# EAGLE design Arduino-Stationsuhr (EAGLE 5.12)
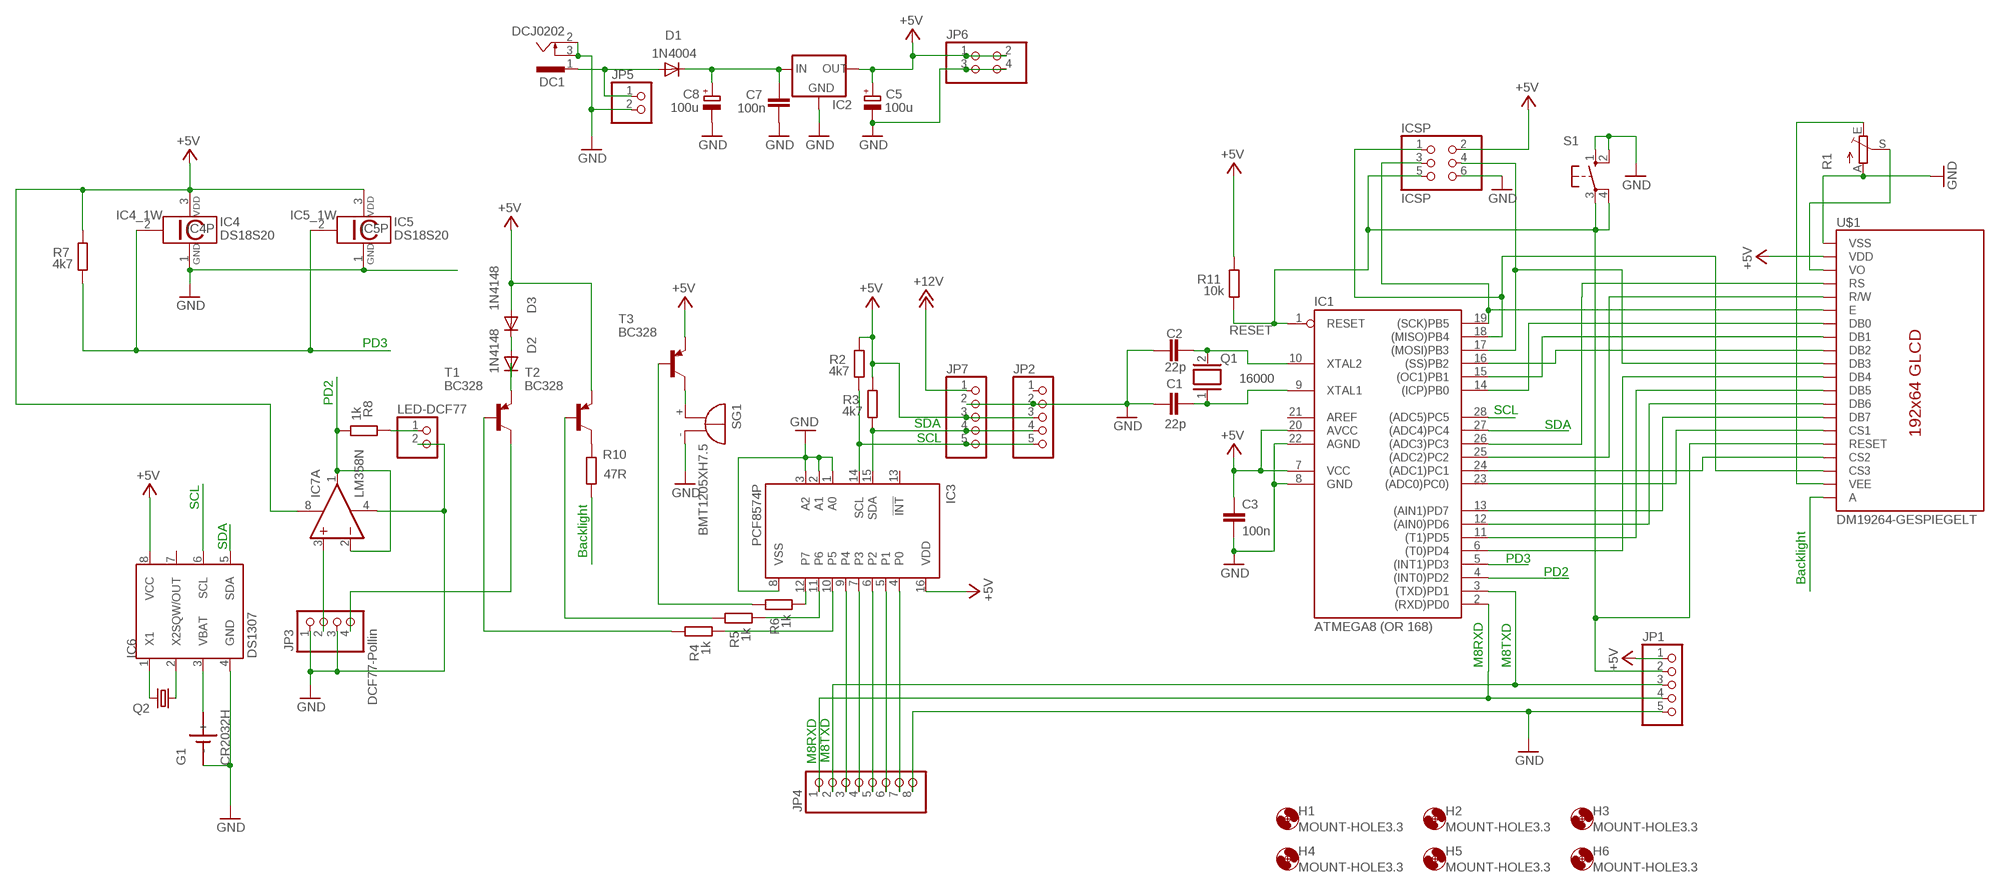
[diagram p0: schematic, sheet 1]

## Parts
C1  22p  C-EU025-024X044  [C025-024X044]
C2  22p  C-EU025-024X044  [C025-024X044]
C3  100n  C-5-1  [C-5-1]
C5  100u  CPOL-EUE3.5-8  [E3,5-8]
C7  100n  C-5-1  [C-5-1]
C8  100u  CPOL-EUE3.5-8  [E3,5-8]
D1  1N4004  1N4148  [DO35-10]
D2  1N4148  1N4148DO35-10  [DO35-10]
D3  1N4148  1N4148DO35-10  [DO35-10]
DC1  DCJ0202  733980-62  [733980-62]
G1  CR2032H  SN2032  [SN2032]
H1  MOUNT-HOLE3.3  [3,3]
H2  MOUNT-HOLE3.3  [3,3]
H3  MOUNT-HOLE3.3  [3,3]
H4  MOUNT-HOLE3.3  [3,3]
H5  MOUNT-HOLE3.3  [3,3]
H6  MOUNT-HOLE3.3  [3,3]
IC1  ATMEGA8 (OR 168)  AT90S4433P  [DIL28-3]
IC2  78XXL  [78XXL]
IC3  PCF8574P  [DIL16]
IC4  DS18S20  [TO92-]
IC5  DS18S20  [TO92-]
IC6  DS1307  DS1307DIL-8  [DIL08]
IC7  LM358N  [DIL08]
ICSP  ICSP  PINHD-2X3  [2X03]
JP1  PINHD-1X5/90  [1X05/90]
JP2  PINHD-1X5  [1X05]
JP3  DCF77-Pollin  PINHD-1X4  [1X04]
JP4  PINHD-1X8  [1X08]
JP5  PINHD-1X2  [1X02]
JP6  PINHD-2X2  [2X02]
JP7  PINHD-1X5  [1X05]
LED-DCF77  PINHD-1X2  [1X02]
Q1  16000  XTAL/S  [QS]
Q2  CRYSTALTC26H  [TC26H]
R1  TRIM_EU-LI10  [LI10]
R2  4k7  R-EU_0207/10  [0207/10]
R3  4k7  R-EU_0207/10  [0207/10]
R4  1k  R-EU_0207/10  [0207/10]
R5  1k  R-EU_0207/10  [0207/10]
R6  1k  R-EU_0207/10  [0207/10]
R7  4k7  R-EU_0207/10  [0207/10]
R8  1k  R-EU_0207/10  [0207/10]
R10  47R  R-EU_0207/10  [0207/10]
R11  10k  R-EU_0207/10  [0207/10]
S1  10-XX  [B3F-10XX]
SG1  BMT1205XH7.5  [BMT1205XH7.5]
T1  BC328  -PNP-TO92-CBE  [TO92-CBE]
T2  BC328  BC328-25  [TO92-EBC]
T3  BC328  BC328-25  [TO92-EBC]
U$1  DM19264-GESPIEGELT  [DM19265-GESPIEGELT]

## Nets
+5V [power]: C3.P$1 C5.+ D3.A IC1.7(VCC) IC1.20(AVCC) IC2.OUT IC3.16(VDD) IC4.3 IC5.3 IC6.8(VCC) IC7.8(P:V+) ICSP.2 JP1.1 JP2.3 JP6.1 JP6.2 JP7.3 R2.2 R3.2 R7.2 R11.2 T2.E T3.E U$1.2(VDD)
+12V: D1.A DC1.1 JP5.1
BACKLIGHT: R10.1 U$1.20(A)
GND: C1.1 C2.1 C3.P$2 C5.- C7.P$1 C8.- DC1.2 DC1.3 G1.- IC1.8(GND) IC1.22(AGND) IC2.GND IC3.1(A0) IC3.2(A1) IC3.3(A2) IC3.8(VSS) IC4.1 IC5.1 IC6.4(GND) IC7.4(P:V-) ICSP.6 JP1.5 JP2.2 JP3.1 JP3.3 JP4.8 JP5.2 JP6.3 JP6.4 JP7.2 LED-DCF77.2 R1.A S1.1(S) S1.2(S1) SG1.- U$1.1(VSS)
M8RXD: IC1.2((RXD)PD0) JP1.4 JP4.1
M8TXD: IC1.3((TXD)PD1) JP1.3 JP4.2
N$1: IC1.18((MISO)PB4) ICSP.1 U$1.18(CS3)
N$2: R1.S U$1.3(VO)
N$3: IC3.9(P4) JP4.3
N$4: IC1.17((MOSI)PB3) ICSP.4 U$1.10(DB3)
N$5: IC1.26((ADC3)PC3) U$1.4(RS)
N$6: C1.2 IC1.9(XTAL1) Q1.1
N$7: C2.2 IC1.10(XTAL2) Q1.2
N$8: IC7.3(A:+IN) JP3.2
N$9: IC1.25((ADC2)PC2) U$1.5(R/W)
N$10: IC1.14((ICP)PB0) U$1.7(DB0)
N$11: IC1.15((OC1)PB1) U$1.8(DB1)
N$12: IC1.16((SS)PB2) U$1.9(DB2)
N$13: IC6.1(X1) Q2.2
N$14: IC1.6((T0)PD4) U$1.11(DB4)
N$15: IC1.11((T1)PD5) U$1.12(DB5)
N$16: IC1.12((AIN0)PD6) U$1.13(DB6)
N$17: IC1.13((AIN1)PD7) U$1.14(DB7)
N$18: IC1.23((ADC0)PC0)) U$1.15(CS1)
N$19: R4.2 T1.B
N$20: IC1.24((ADC1)PC1) U$1.17(CS2)
N$21: IC6.2(X2) Q2.1
N$22: G1.+ IC6.3(VBAT)
N$23: IC3.4(P0) JP4.7
N$24: IC3.5(P1) JP4.6
N$25: IC3.6(P2) JP4.5
N$26: IC3.7(P3) JP4.4
N$28: IC3.10(P5) R4.1
N$29: IC3.11(P6) R5.1
N$30: IC3.12(P7) R6.1
N$31: D2.C T1.E
N$32: R5.2 T2.B
N$33: R6.2 T3.B
N$34: JP3.4 T1.C
N$36: SG1.+ T3.C
N$41: LED-DCF77.1 R8.2
N$42: R1.E U$1.19(VEE)
N$53: R10.2 T2.C
N$54 [power]: D2.A D3.C
PD2: IC1.4((INT0)PD2) IC7.1(A:OUT) IC7.2(A:-IN) R8.1
PD3: IC1.5((INT1)PD3) IC4.2 IC5.2 R7.1
RESET: IC1.1(RESET) ICSP.5 JP1.2 R11.1 S1.3(P) S1.4(P1) U$1.16(RESET)
SCK: IC1.19((SCK)PB5) ICSP.3 U$1.6(E)
SCL: IC1.28((ADC5)PC5) IC3.14(SCL) IC6.6(SCL) JP2.5 JP7.5 R2.1
SDA: IC1.27((ADC4)PC4) IC3.15(SDA) IC6.5(SDA) JP2.4 JP7.4 R3.1
VIN [power]: C7.P$2 C8.+ D1.C IC2.IN JP7.1 ; supply symbol labelled +12V
Unconnected: IC3.13(!INT) IC6.7(SQW/OUT) IC7.5(B:+IN) IC7.6(B:-IN) IC7.7(B:OUT) JP2.1

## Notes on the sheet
- PD3
- PD2
- SCL
- SDA | SDA
- SCL
- SCL
- SDA
- Backlight
- PD3
- PD2
- Backlight
- M8RXD | M8TXD
- M8RXD | M8TXD

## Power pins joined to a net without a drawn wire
AREF: IC1.21(AREF)

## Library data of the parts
C1 C2 = rcl:C-EU: CAPACITOR, European symbol
C3 C7 = papa:C-5-1
C5 C8 = rcl:CPOL-EU: POLARIZED CAPACITOR, European symbol
D1 = papa:1N4148: DIODE
D2 D3 = diode:1N4148: DIODE
DC1 = con-conrad:73398?: FEMALE PRINT CONNECTOR Niedervolt-Steckverbinder Distributor Conrad
G1 = sn2032:SN2032: LI BATTERY
H1-H6 = holes:MOUNT-HOLE: MOUNTING HOLE with drill center marker
IC1 = atmel:AT90S4433: MICROCONTROLLER 4 Kbytes FLASH 128 bytes SRAM 256 bytes EEPROM UART 6-channel 10 bit ADC
IC2 = v-reg:78XXL: VOLTAGE REGULATOR
IC3 = micro-philips:PCF8574: I2C-Bus Remote 8-bit I/O expander http://www.semiconductors.philips.com/acrobat_download/datasheets/PCF8574_4.pdf; MPN: PCF8574PN; OC_FARNELL: 204020; OC_NEWARK: 11N8515
IC4 IC5 = 1wire:DS18S20: High Precision Digital Thermometer This chip provides a onewire thermosensor with approx. 0.5°C accuracy.A programmable over/undertemperure alarm is available. Notes: Vdd must be applied for accurate measurements at low temperatures, as the parasite power circuit otherwise heats the sensor. If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
IC6 = dallas-1:DS1307: I2C Serial RTC w/56 bytes battery backed RAM
IC7 = linear:LM358: OP AMP also LM158; LM258; LM2904 Source: http://cache.national.com/ds/LM/LM158.pdf
ICSP = pinhead:PINHD-2X3: PIN HEADER
JP1 JP2 JP7 = pinhead:PINHD-1X5: PIN HEADER
JP3 = pinhead:PINHD-1X4: PIN HEADER
JP4 = pinhead:PINHD-1X8: PIN HEADER
JP5 LED-DCF77 = pinhead:PINHD-1X2: PIN HEADER
JP6 = pinhead:PINHD-2X2: PIN HEADER
Q1 = special:XTAL/S: CRYSTAL
Q2 = crystal:CRYSTAL: CRYSTAL; OC_FARNELL: unknown; OC_NEWARK: unknown
R1 = pot:TRIM_EU-: POTENTIOMETER
R2-R8 R10 R11 = rcl:R-EU_: RESISTOR, European symbol
S1 = switch-omron:10-XX: OMRON SWITCH
SG1 = buzzer:BMT1205XH7.5: MAGNETIC TRANSDUCER; OC_FARNELL: unknown; OC_NEWARK: unknown
T1 = transistor-neu-to92:*-PNP-: PNP Transistror
T2 T3 = transistor-pnp:BC328*: PNP Transistror
U$1 = DM19264:DM19264-GESPIEGELT

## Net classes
1 power: width 0.61 mm

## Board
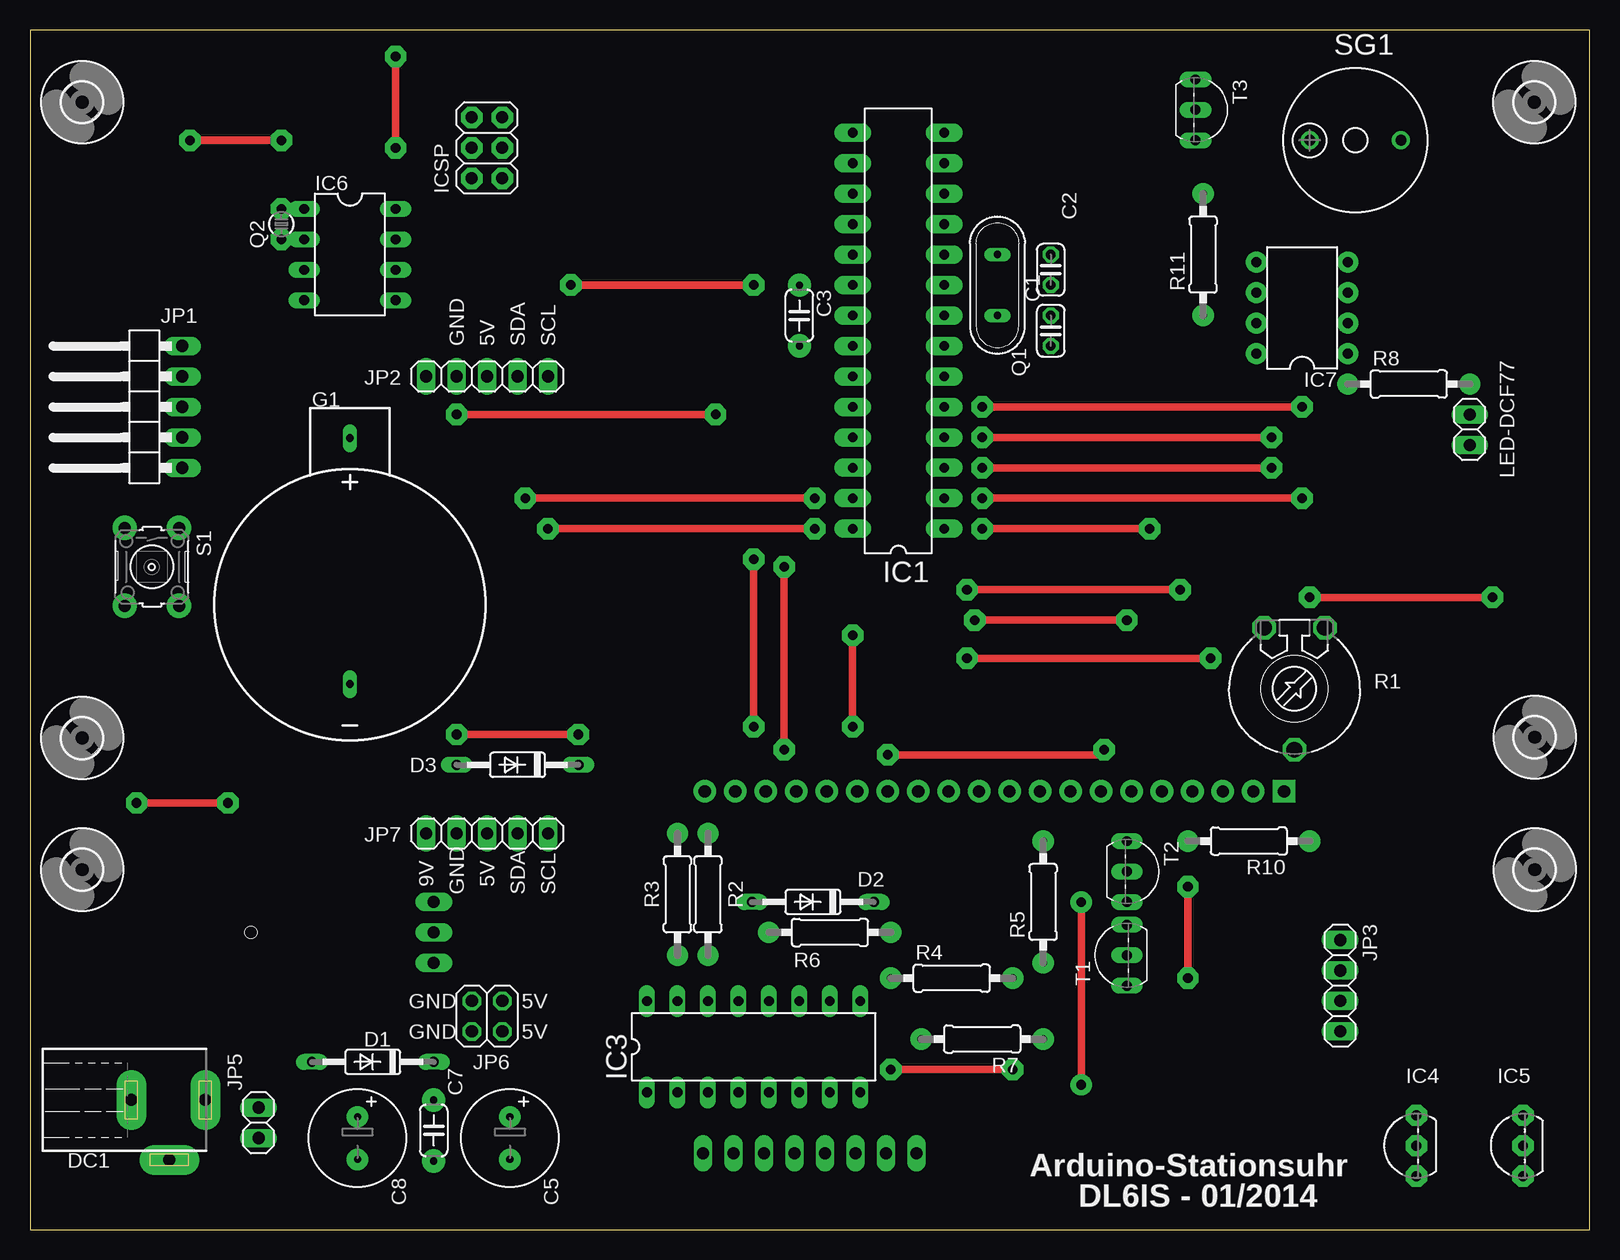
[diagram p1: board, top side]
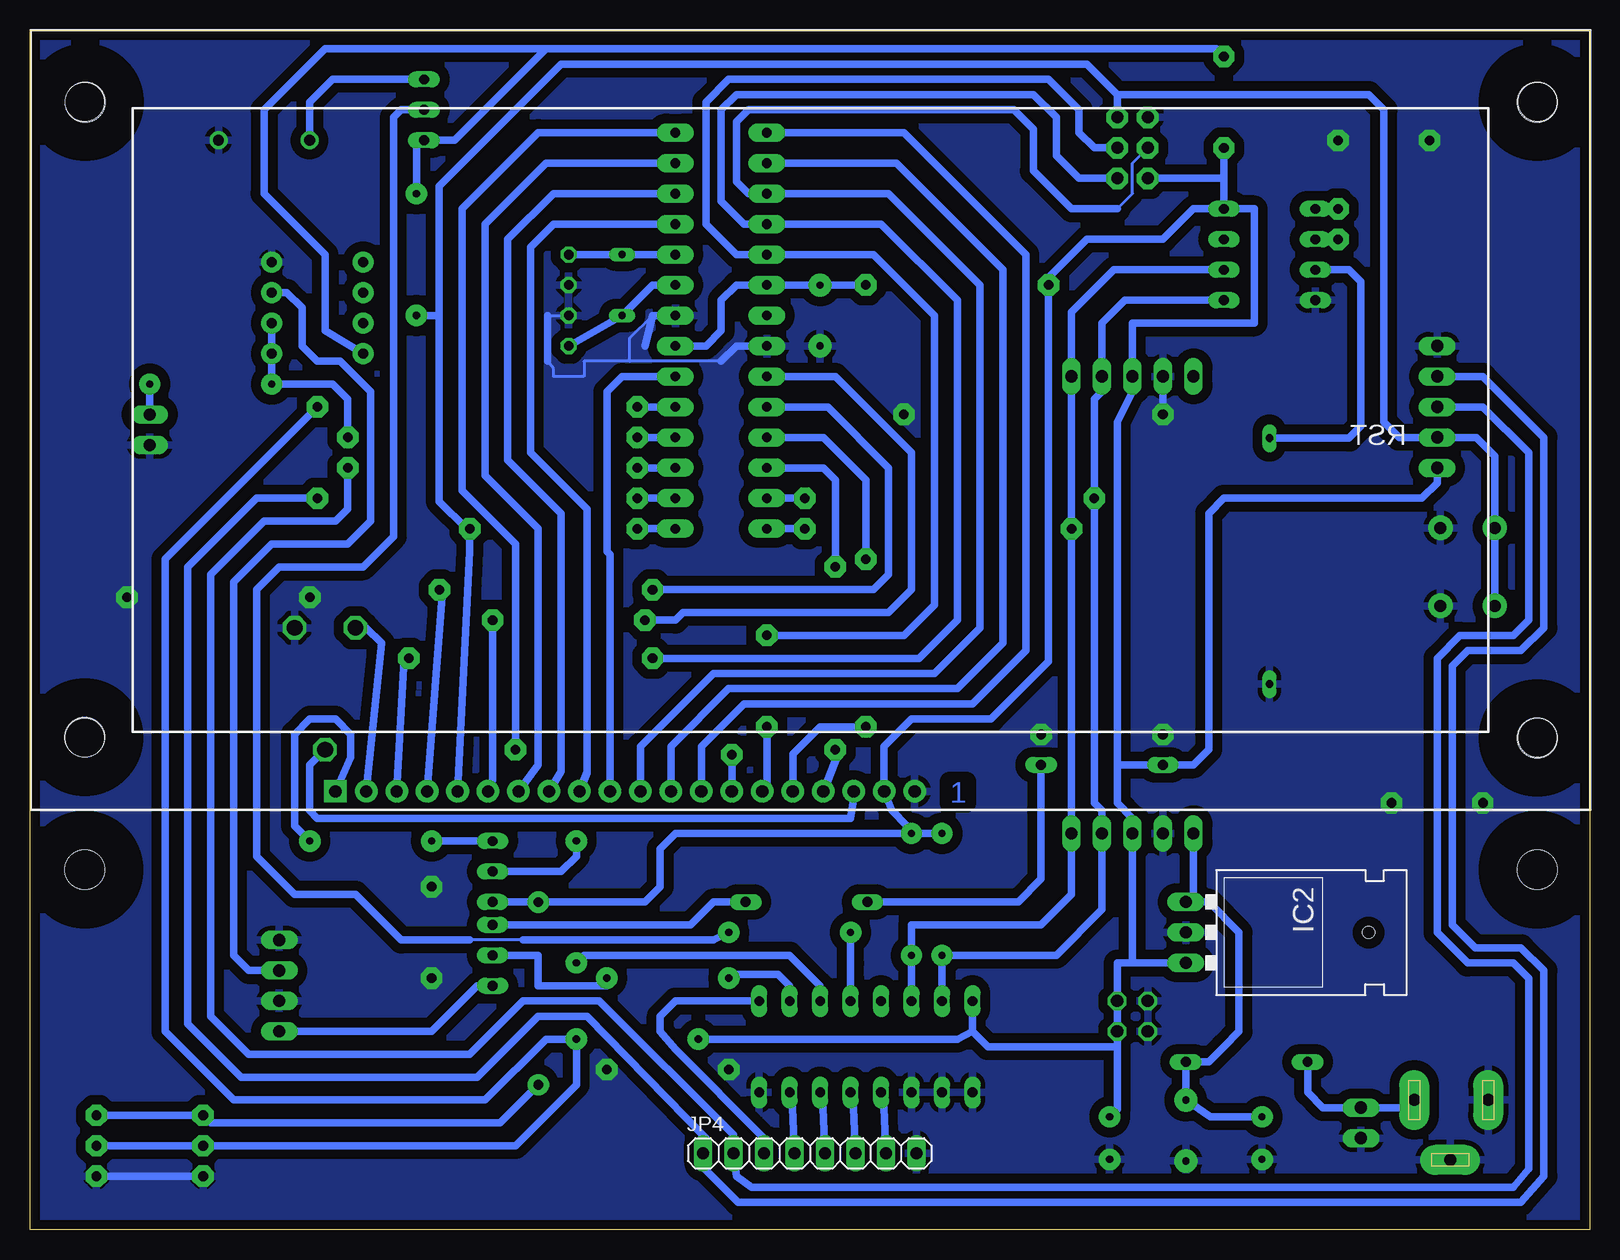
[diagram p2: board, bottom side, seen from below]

Size 130 x 100 mm. Coordinates in mm from the lower left corner, seen from the top.
Outline: 0,0 130,0 130,100 0,100 0,0
Copper layers (1*16): Top 0.035mm / dielectric 1.5mm / Bottom 0.035mm
Design rules "default *": minimum track width 10mil, minimum drill 24mil, track to track 8mil, track to pad 8mil, pad to pad 8mil, via to via 8mil, smd to smd 8mil, copper to edge 20mil, drill to drill 8mil, minimum pad ring 10mil, minimum via ring 10mil, stop-mask expansion 4mil, vias tented up to drill 0mil, thermal gap 16mil
Holes 1 mm at 18.41,24.77

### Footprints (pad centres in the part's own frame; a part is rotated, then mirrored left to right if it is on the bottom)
C025-024X044 = drill 0.813 octagon: 1 -1.27,0; 2 1.27,0
C-5-1 = drill 0.6 pad 1.93 round: P$1 -2.54,0; P$2 2.54,0
E3,5-8 = drill 0.6 pad 1.778 round: + -1.778,0; - 1.778,0
DO35-10 = drill 0.813 long: A 5.08,0; C -5.08,0
733980-62 = drill 1 pad 2.5 long: 1 0,8.57; 2 0,2.42; 3 5,5.57
SN2032 = drill 0.65 long: + 0,13.9; - 0,-6.6
3,3 = hole 3.3: 0,0
DIL28-3 = drill 0.813 pad 1.524 long: 1 -16.51,-3.81; 2 -13.97,-3.81; 3 -11.43,-3.81; 4 -8.89,-3.81; 5 -6.35,-3.81; 6 -3.81,-3.81; 7 -1.27,-3.81; 8 1.27,-3.81; 9 3.81,-3.81; 10 6.35,-3.81; 11 8.89,-3.81; 12 11.43,-3.81; 13 13.97,-3.81; 14 16.51,-3.81; 15 16.51,3.81; 16 13.97,3.81; 17 11.43,3.81; 18 8.89,3.81; 19 6.35,3.81; 20 3.81,3.81; 21 1.27,3.81; 22 -1.27,3.81; 23 -3.81,3.81; 24 -6.35,3.81; 25 -8.89,3.81; 26 -11.43,3.81; 27 -13.97,3.81; 28 -16.51,3.81
78XXL = drill 1.016 long: GND 0,-3.81; IN -2.54,-3.81; OUT 2.54,-3.81
DIL16 = drill 0.813 long: 1 -8.89,-3.81; 2 -6.35,-3.81; 3 -3.81,-3.81; 4 -1.27,-3.81; 5 1.27,-3.81; 6 3.81,-3.81; 7 6.35,-3.81; 8 8.89,-3.81; 9 8.89,3.81; 10 6.35,3.81; 11 3.81,3.81; 12 1.27,3.81; 13 -1.27,3.81; 14 -3.81,3.81; 15 -6.35,3.81; 16 -8.89,3.81
TO92- = drill 0.813 octagon: 1 -2.54,0; 2 0,0; 3 2.54,0
DIL08 = drill 0.813 long: 1 -3.81,-3.81; 2 -1.27,-3.81; 3 1.27,-3.81; 4 3.81,-3.81; 5 3.81,3.81; 6 1.27,3.81; 7 -1.27,3.81; 8 -3.81,3.81
DIL08' = drill 0.813 pad 1.27 round: 1 -3.81,-3.81; 2 -1.27,-3.81; 3 1.27,-3.81; 4 3.81,-3.81; 5 3.81,3.81; 6 1.27,3.81; 7 -1.27,3.81; 8 -3.81,3.81
2X03 = drill 1 pad 1.778 octagon: 1 -2.54,-1.27; 2 -2.54,1.27; 3 0,-1.27; 4 0,1.27; 5 2.54,-1.27; 6 2.54,1.27
1X05/90 = drill 1.016 long: 1 -5.08,-3.81; 2 -2.54,-3.81; 3 0,-3.81; 4 2.54,-3.81; 5 5.08,-3.81
1X05 = drill 1.016 long: 1 -5.08,0; 2 -2.54,0; 3 0,0; 4 2.54,0; 5 5.08,0
1X04 = drill 1.016 long: 1 -3.81,0; 2 -1.27,0; 3 1.27,0; 4 3.81,0
1X08 = drill 1.016 long: 1 -8.89,0; 2 -6.35,0; 3 -3.81,0; 4 -1.27,0; 5 1.27,0; 6 3.81,0; 7 6.35,0; 8 8.89,0
1X02 = drill 1.016 long: 1 -1.27,0; 2 1.27,0
2X02 = drill 1.016 octagon: 1 -1.27,-1.27; 2 -1.27,1.27; 3 1.27,-1.27; 4 1.27,1.27
QS = drill 0.61 long: 1 -2.54,0; 2 2.54,0
TC26V = drill 0.813 round: 1 -1.27,0; 2 1.27,0
LI10 = drill 1.321 octagon: A -2.54,-5.08; E 2.54,-5.08; S 0,5.08
0207/10 = drill 0.6 pad 1.778 round: 1 -5.08,0; 2 5.08,0
B3F-10XX = drill 1 pad 2.032 round: 1 -3.251,2.261; 2 3.251,2.261; 3 -3.251,-2.261; 4 3.251,-2.261
BMT1205XH7.5 = drill 0.9 pad 1.5 round: + 3.8,0; - -3.8,0
TO92-CBE = drill 0.813 long: B 0,0; C -2.54,0; E 2.54,0
TO92-EBC = drill 0.813 long: B 0,-1.27; C -2.54,-1.27; E 2.54,-1.27
DM19265-GESPIEGELT = drill 1.016 pad 1.88 round: 1 56.495,1.53; 2 59.035,1.53; 3 61.575,1.53; 4 64.115,1.53; 5 66.655,1.53; 6 69.195,1.53; 7 71.735,1.53; 8 74.275,1.53; 9 76.815,1.53; 10 79.355,1.53; 11 81.895,1.53; 12 84.435,1.53; 13 86.975,1.53; 14 89.515,1.53; 15 92.055,1.53; 16 94.595,1.53; 17 97.135,1.53; 18 99.675,1.53; 19 102.215,1.53 | drill 1.016 pad 1.88 square: 20 104.775,1.53 | hole 3.2: 125.675,59; 125.675,6; 4.575,59; 4.575,6

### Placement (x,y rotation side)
C1  85.09,74.93 270 top
C2  85.09,80.01 90 top
C3  64.14,76.2 270 top
C5  40.01,7.62 270 top
C7  33.66,8.26 90 top
C8  27.3,7.62 270 top
D1  28.57,13.97 180 top
D2  65.27,27.3 180 top
D3  40.64,38.73 180 top
DC1  6.04,10.79 270 top
G1  26.67,52.07 0 top
H1  4.34,30 0 top
H2  125.43,30 0 top
H3  4.34,93.98 0 top
H4  125.39,93.98 0 top
H5  4.34,40.98 0 top
H6  125.43,41.04 0 top
IC1  72.39,74.93 90 top
IC2  29.84,24.77 270 bottom
IC3  60.33,15.24 0 top
IC4  115.57,6.99 90 top
IC5  124.46,6.99 90 top
IC6  26.67,81.28 270 top
IC7  LM358N  [DIL08']  106.05,76.83 90 top
ICSP  38.1,90.17 90 top
JP1  8.89,68.58 90 top
JP2  38.1,71.12 0 top
JP3  109.22,20.32 270 top
JP4  65,6.35 0 bottom
JP5  19.05,8.89 270 top
JP6  38.1,17.78 180 top
JP7  38.1,33.02 0 top
LED-DCF77  120.02,66.67 270 top
Q1  80.64,78.74 90 top
Q2  [TC26V]  20.95,83.82 90 top
R1  105.41,45.09 180 top
R2  56.52,27.94 90 top
R3  53.98,27.94 90 top
R4  76.83,20.95 0 top
R5  84.45,27.3 90 top
R6  66.67,24.77 0 top
R7  79.38,15.88 180 top
R8  114.94,70.48 0 top
R10  101.6,32.38 180 top
R11  97.79,81.28 90 top
S1  10.16,55.24 270 top
SG1  110.49,90.81 180 top
T1  91.44,22.86 90 top
T2  92.71,29.84 270 top
T3  98.42,93.34 270 top
U$1  -0.24,35 0 top

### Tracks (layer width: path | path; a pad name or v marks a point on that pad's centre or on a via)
+5V  (via drill 0.8 pad 1.78)
  Top 0.61: v45.09,78.74 v60.33,78.74 | v30.48,90.17 v30.48,97.79 | v87.63,27.3 v87.63,12.06
  Bottom 0.61: v60.33,78.74 C3.P$1 IC1.20 71.12,78.74 72.39,77.47 72.39,74.93 73.66,73.66 IC1.7 | R2.2 R3.2 | R2.2 56.89,33.66 58.16,34.92 U$1.2 58.8,40.27 56.52,42.55 49.9,42.55 45.09,47.35 v45.09,78.74 45.09,79.38 41.91,82.55 35.56,82.55 33.02,85.09 IC6.8 | IC6.8 27.94,85.09 27.94,75.56 38.1,75.56 JP2.3 38.1,69.85 39.37,67.31 39.37,38.73 | 30.48,87.63 v30.48,90.17 | 30.48,87.63 ICSP.2 | IC6.8 30.48,87.63 | v30.48,97.79 31.11,98.42 87,98.42 | 51.44,16.51 50.16,15.24 39.37,15.24 | 51.44,16.51 IC3.16 | R11.2 97.79,90.81 T3.E 94.61,90.81 87,98.42 | 39.37,38.73 D3.A 33.02,38.73 31.75,40.01 31.75,59.69 30.48,60.96 13.97,60.96 12.7,62.23 JP1.1 | 38.1,22.23 39.37,22.23 JP6.1 JP6.2 39.37,15.24 | 38.1,22.23 IC2.OUT | R2.2 76.2,33.02 77.47,31.75 77.47,28.57 78.74,27.3 T2.E v87.63,27.3 | IC5.3 IC4.3 114.94,8.89 90.81,8.89 v87.63,12.06 | R7.2 52.7,15.88 51.44,16.51 | 39.37,15.24 39.37,10.03 C5.+ | 38.1,22.23 JP7.3 38.1,34.29 39.37,35.56 39.37,38.73 | IC7.8 105.41,74.93 105.41,81.28 110.49,86.36 110.49,93.34 105.41,98.42 87,98.42
+12V
  Bottom 0.61: D1.A 23.5,11.43 22.23,10.16 JP5.1 15.24,10.16 DC1.1
BACKLIGHT
  Bottom 0.61: U$1.20 103.27,39.37 103.27,41.27 104.53,42.55 106.68,42.55 107.95,41.27 107.95,33.66 R10.1
GND  (via drill 0.8 pad 1.78)
  Top 0.61: v13.34,90.81 v20.95,90.81 | v8.89,35.56 v16.51,35.56 | v35.56,41.27 v45.72,41.27 | v35.56,67.94 v57.15,67.94 | v106.68,52.7 v121.92,52.7 | v71.75,13.34 v81.92,13.34 | v96.52,20.95 v96.52,28.57
  Bottom 0.254: 72.39,72.39 80.01,72.39 | 80.01,72.39 83.82,72.39 83.82,71.12 86.36,71.12 86.36,71.75 86.85,72.39 | 78.11,76.2 80.01,74.3 80.01,72.39 | 86.85,76.2 C1.1
  Bottom 0.61: IC4.1 IC5.1 | v35.56,67.94 JP2.2 | 78.74,73.66 78.11,76.2 IC1.8 | IC1.22 71.12,73.66 72.39,72.39 | 86.85,72.39 86.85,76.2
  other vias: 115.57,4.45 124.46,4.45 109.86,80.64
  pour Bottom (isolate 0.813): 0,100.33 130,100.33 130,0 1,0 0,1
M8RXD  (via drill 0.8 pad 1.78)
  Top 0.61: v106.05,60.96 v79.38,60.96
  Bottom 0.61: JP1.4 8.89,71.12 3.81,66.04 3.81,50.16 5.71,48.26 10.16,48.26 11.43,46.99 11.43,25.4 9.53,23.5 5.71,23.5 3.81,21.59 3.81,4.45 5.71,2.27 70.98,2.27 73.89,5.17 JP4.1 73.66,7.62 83.55,17.78 87.63,17.78 92.71,12.7 112.39,12.7 116.84,17.14 116.84,55.24 111.12,60.96 v106.05,60.96 | v79.38,60.96 IC1.2
M8TXD  (via drill 0.8 pad 1.78)
  Top 0.61: v103.5,63.5 v79.38,63.5
  Bottom 0.61: JP1.3 8.89,68.58 5.08,64.77 5.08,50.8 6.35,49.53 10.79,49.53 12.7,47.62 12.7,24.77 10.16,22.23 6.35,22.23 5.08,20.95 5.08,5.08 6.35,3.54 69.85,3.54 71.12,4.45 JP4.2 71.35,7.89 82.55,19.05 88.9,19.05 93.34,14.61 111.76,14.61 114.94,17.78 114.94,54.61 110.49,59.05 104.5,59.05 103.5,60.05 v103.5,63.5 | v79.38,63.5 IC1.3
N$1  (via drill 0.8 pad 1.78)
  Top 0.61: v78.11,47.62 v98.42,47.62
  Bottom 0.61: v78.11,47.62 55.88,47.62 52.7,50.8 52.7,77.47 59.05,83.82 IC1.18 70.48,83.82 72.39,85.72 72.39,93.34 71.12,94.61 46.35,94.61 44.45,92.71 44.45,89.53 42.55,87.63 ICSP.1 | v98.42,47.62 98.8,47.62 U$1.18
N$2
  Bottom 0.61: U$1.3 61.34,35.82 61.59,34.29 106.05,34.29 106.68,34.92 106.68,38.1 106.68,38.73 R1.S
N$3
  Bottom 0.61: JP4.3 68.81,7.62 76.2,15.01 77.47,16.51 77.47,17.78 76.2,19.05 IC3.9
N$4
  Bottom 0.254: 39.37,85.09 38.1,86.36 38.1,88.9 ICSP.4
  Bottom 0.61: 39.37,85.09 43.18,85.09 46.35,88.27 46.35,91.71 47.99,93.34 70.12,93.34 71.12,92.34 71.12,87.36 70.12,86.36 IC1.17 58.42,86.36 50.8,78.74 50.8,50.16 54.61,46.35 73.03,46.35 79.11,40.27 U$1.10
N$5  (via drill 0.8 pad 1.78)
  Top 0.61: v62.87,40.01 v62.87,55.24
  Bottom 0.61: IC1.26 63.87,63.5 62.87,62.5 v62.87,55.24 | v62.87,40.01 62.6,39.74 U$1.4
N$6
  Bottom 0.61: C1.2 Q1.1 78.11,78.74 IC1.9
N$7
  Bottom 0.61: IC1.10 Q1.2 C2.2
N$8
  Bottom 0.61: IC7.3 108.58,78.11 107.31,76.83 107.31,73.66 106.05,72.39 104.14,72.39 101.6,69.85 101.6,59.05 103.5,57.15 109.86,57.15 113.03,53.98 113.03,22.86 111.76,21.59 JP3.2
N$9  (via drill 0.8 pad 1.78)
  Top 0.61: v60.33,41.91 v60.33,55.88
  Bottom 0.61: IC1.25 63.87,66.04 60.33,62.5 v60.33,55.88 | v60.33,41.91 64.14,41.91 66.42,39.64 U$1.5
N$10  (via drill 0.8 pad 1.78)
  Top 0.61: v71.5,39.58 89.11,39.58 v89.53,40.01
  Bottom 0.61: U$1.7 v71.5,39.58 | IC1.14 87.63,91.44 93.98,85.09 93.98,61.59 89.53,57.15 89.53,55.24 89.53,54.61 v89.53,40.01
N$11
  Bottom 0.61: IC1.15 57.15,91.44 46.99,81.28 46.99,48.26 51.44,43.81 70.48,43.81 74.03,40.27 U$1.8
N$12
  Bottom 0.61: IC1.16 57.78,88.9 48.9,80.01 48.9,48.9 52.7,45.09 71.77,45.09 76.58,40.27 U$1.9
N$13
  Bottom 0.61: Q2.2 IC6.1
N$14
  Bottom 0.61: IC1.6 80.64,71.12 81.92,69.85 81.92,56.52 81.66,56.26 81.66,44.45 U$1.11
N$15
  Bottom 0.61: U$1.12 83.56,38.1 83.56,60.06 83.82,60.33 88.27,64.77 88.27,81.92 86.36,83.82 IC1.11
N$16
  Bottom 0.61: IC1.12 81.92,86.36 86.36,86.36 90.17,82.55 90.17,64.14 85.72,59.69 85.72,53.98 85.72,38.17 U$1.13
N$17
  Bottom 0.61: IC1.13 78.74,88.9 87,88.9 92.08,83.82 92.08,62.87 87.63,58.42 87.63,57.78 87.63,48.9 87.63,40.01 87.63,38.73 U$1.14
N$18  (via drill 0.8 pad 1.78)
  Top 0.61: v78.74,50.8 v91.44,50.8
  Bottom 0.61: v78.74,50.8 76.2,50.8 75.56,51.44 58.42,51.44 56.52,53.34 56.52,64.77 62.87,71.12 IC1.23 | 91.18,50.8 v91.44,50.8 91.44,37.42 U$1.15
N$19
  Bottom 0.61: R4.2 81.92,20.32 87.63,20.32 87.63,22.86 T1.B
N$20  (via drill 0.8 pad 1.78)
  Top 0.61: v78.11,53.34 v95.89,53.34
  Bottom 0.61: v78.11,53.34 59.69,53.34 58.42,54.61 58.42,63.5 63.5,68.58 IC1.24 | v95.89,53.34 95.62,53.34 U$1.17
N$21
  Bottom 0.61: Q2.1 IC6.2
N$22
  Bottom 0.61: IC6.3 20.05,80.01 19.05,79.01 19.05,72.39 19.05,66.97 20.05,65.97 G1.+
N$23
  Bottom 0.61: IC3.4 58.83,10.16 JP4.7
N$24
  Bottom 0.61: IC3.5 61.37,10.16 JP4.6
N$25
  Bottom 0.61: IC3.6 63.91,10.16 JP4.5
N$26
  Bottom 0.61: IC3.7 66.44,10.16 JP4.4
N$27  (via drill 0.8 pad 1.78)
  other vias: 102.23,80.64
N$28
  Bottom 0.61: IC3.10 66.67,20.32 67.63,21.27 72.07,21.27 R4.1
N$29
  Bottom 0.61: R5.1 83.82,22.86 66.67,22.86 64.14,20.32 IC3.11
N$30
  Bottom 0.61: IC3.12 61.59,20.95 61.59,22.23 R6.1
N$31
  Bottom 0.61: D2.C 73.03,27.3 74.93,25.4 T1.E
N$32
  Bottom 0.61: R5.2 84.45,31.11 85.72,29.84 T2.B
N$33
  Bottom 0.254: 88.9,24.13 93.34,24.13
  Bottom 0.61: R6.2 73.03,24.13 88.9,24.13 | 93.34,24.13 99.06,24.13 102.87,27.94 107.95,27.94 111.12,31.11 111.12,53.34 109.22,55.24 102.23,55.24 99.69,57.78 99.69,92.71 99.06,93.34 T3.B
N$34
  Bottom 0.61: T1.C 92.71,20.32 96.52,16.51 JP3.4
N$35  (via drill 0.8 pad 1.78)
  other vias: 102.23,78.11
N$36
  Bottom 0.61: T3.C 104.78,95.89 106.68,93.98 106.68,91.45 SG1.+
N$37  (via drill 0.8 pad 1.78)
  other vias: 102.23,75.56
N$38  (via drill 0.8 pad 1.78)
  other vias: 102.23,73.03
N$39  (via drill 0.8 pad 1.78)
  other vias: 109.86,75.56
N$40  (via drill 0.8 pad 1.78)
  other vias: 109.86,78.11
N$41
  Bottom 0.61: LED-DCF77.1 R8.2
N$42
  Bottom 0.61: U$1.19 100.7,48.9 101.97,50.16 R1.E
N$43
  pour Bottom: 116.84,87.63 125.09,87.63 125.09,74.3 116.84,74.3
N$44  (via drill 0.8 pad 1.78)
  other vias: 124.46,6.99
N$45  (via drill 0.8 pad 1.78)
  other vias: 124.46,9.53
N$47  (via drill 0.8 pad 1.78)
  other vias: 115.57,6.99
N$48  (via drill 0.8 pad 1.78)
  other vias: 115.57,9.53
N$49  (via drill 0.8 pad 1.78)
  other vias: 20.95,85.09
N$50  (via drill 0.8 pad 1.78)
  other vias: 20.95,82.55
N$53
  Bottom 0.61: T2.C R10.2
N$54
  Bottom 0.61: D3.C 45.72,29.21 47.62,27.3 D2.A
PD2  (via drill 0.8 pad 1.78)
  Top 0.61: v79.38,66.04 v103.5,66.04
  Bottom 0.61: IC1.4 v79.38,66.04 | IC7.2 v109.86,73.03 R8.1 104.78,70.48 103.5,69.22 v103.5,66.04
PD3  (via drill 0.8 pad 1.78)
  Top 0.61: v106.05,68.58 v79.38,68.58
  Bottom 0.61: v79.38,68.58 IC1.5 | IC5.2 IC4.2 89.53,6.99 84.45,12.06 R7.1 87,15.88 92.08,10.79 113.03,10.79 118.75,16.51 118.75,55.88 v106.05,68.58
RESET  (via drill 0.8 pad 1.78)
  Top 0.61: v93.34,58.42 v79.38,58.42
  Bottom 0.61: S1.4 S1.3 7.9,64.49 9.45,66.04 JP1.2 15.88,66.04 17.14,67.31 17.14,93.34 18.41,94.61 39.37,94.61 | v79.38,58.42 IC1.1 | 39.37,94.61 ICSP.5 | 39.37,94.61 41.91,97.16 85.72,97.16 95.89,87 95.89,76.2 | 95.89,76.2 R11.1 | 95.89,76.2 95.89,60.69 93.61,58.42 v93.34,58.42 93.34,56.52 U$1.16
SCK  (via drill 0.8 pad 1.78)
  Top 0.61: v68.58,41.91 v68.58,49.53
  Bottom 0.61: v68.58,49.53 57.15,49.53 54.61,52.07 54.61,76.2 59.69,81.28 IC1.19 71.12,81.28 73.66,83.82 73.66,93.98 71.75,95.89 45.09,95.89 42.55,93.34 42.55,91.44 41.27,90.17 ICSP.3 | v68.58,41.91 68.58,36.83 68.88,36.53 U$1.6
SCL  (via drill 0.8 pad 1.78)
  Top 0.61: v43.18,58.42 v65.41,58.42
  Bottom 0.61: IC3.14 R2.1 56.52,23.5 56.52,25.4 50.16,25.4 48.9,25.4 45.72,25.4 43.18,27.94 JP7.5 | JP7.5 43.18,34.29 | JP2.5 v43.18,58.42 43.18,35.56 43.18,34.29 | JP2.5 43.18,74.93 | 43.18,74.93 43.18,76.47 39.64,80.01 IC6.6 | v65.41,58.42 IC1.28 | JP7.5 43.18,34.29 | JP2.5 43.18,74.93
SDA  (via drill 0.8 pad 1.78)
  Top 0.61: v41.27,60.96 v65.41,60.96
  Bottom 0.61: IC3.15 R3.1 44.45,22.86 40.64,26.67 JP7.4 40.64,34.92 41.27,35.56 v41.27,60.96 41.27,69.22 40.64,69.85 JP2.4 40.64,75.56 38.73,77.47 IC6.5 | v65.41,60.96 IC1.27
VIN
  Bottom 0.61: C8.+ 31.62,9.4 C7.P$2 33.66,13.34 D1.C 31.75,13.97 30.48,15.24 29.21,16.51 29.21,24.77 31.75,27.3 IC2.IN 33.02,27.3 JP7.1

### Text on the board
Bottom: 1
tNames: GND | 5V | SDA | SCL | 9V | 5V | GND | SDA | SCL | GND | 5V | GND | 5V | Arduino-Stationsuhr | DL6IS - 01/2014
bNames: RST
tValues: 7,5 | 7,5 | 1 | 15 | GND | RX | TX | 5V | 17,5 | 15 | 12,5 | 15 | 7,5 | 10 | 7,5 | 7,5 | 15 | 10
bRestrict: 09/2014 | DL6IS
